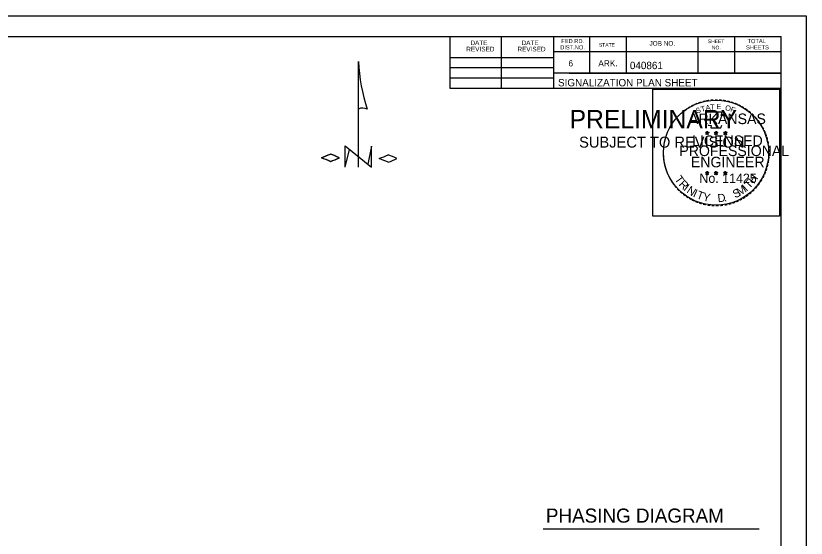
# Model space of a CAD drawing. Extents: x 641001 to 642001, y 326365 to 327005.
# Drawn here: x 641552.4 to 642001.4, y 326708.5 to 327005 of the extents above; entities that cross this region are included whole.
import ezdxf

# ---------------------------------------------------------------- set-up
doc = ezdxf.new("R2010")
doc.units = 0
for name, color, linetype in [('R_Border', 7, 'Continuous'), ('R_Border PE', 7, 'Continuous'), ('R_Border Prem', 7, 'Continuous'), ('R_No Plot', 7, 'Continuous'), ('T_Drafting', 7, 'Continuous'), ('T_Notes', 7, 'Continuous')]:
    doc.layers.add(name, color=color, linetype=linetype)

msp = doc.modelspace()

# ---------------------------------------------------------------- linework, layer by layer
at = {"layer": 'R_Border'}
for p, q in [((641038.57, 326993.34), (641987.11, 326993.34)), ((641799.19, 326963.7), (641799.19, 326993.34)), ((641828.23, 326963.7), (641828.23, 326993.34)), ((641857.81, 326993.34), (641857.81, 326963.7)), ((641878.33, 326993.34), (641878.33, 326972.52)), ((641899.15, 326993.34), (641899.15, 326972.52)), ((641939.89, 326993.34), (641939.89, 326972.52)), ((641960.71, 326993.34), (641960.71, 326972.52)), ((641987.11, 326376.96), (641987.11, 326993.34)), ((641987.11, 326984.52), (641857.81, 326984.52)), ((641987.11, 326984.58), (641987.11, 326984.58)), ((641799.19, 326981.28), (641857.81, 326981.28)), ((641799.19, 326975.7), (641857.81, 326975.7)), ((641799.19, 326969.88), (641857.81, 326969.88)), ((641987.11, 326972.52), (641857.81, 326972.52)), ((641866.69, 326972.52), (641987.11, 326972.52)), ((641987.11, 326963.7), (641799.19, 326963.7))]:
    msp.add_line(p, q, dxfattribs=at)
at = {"layer": 'R_Border PE'}
for p, q in [((641944.09, 326938.78), (641945.13, 326938.45)), ((641944.09, 326938.78), (641944.85, 326938.65)), ((641944.09, 326938.78), (641944.8, 326938.41)), ((641944.49, 326937.56), (641945.13, 326938.45)), ((641944.49, 326937.56), (641944.86, 326938.29)), ((641944.49, 326937.56), (641945.13, 326938.21)), ((641945.13, 326939.54), (641945.01, 326938.79)), ((641945.13, 326938.45), (641945.13, 326939.54)), ((641945.13, 326939.54), (641945.28, 326938.79)), ((641946.18, 326938.78), (641945.13, 326938.45)), ((641945.77, 326937.56), (641945.13, 326938.45)), ((641945.77, 326937.56), (641945.13, 326938.2)), ((641946.18, 326938.78), (641945.32, 326938.63)), ((641945.77, 326937.56), (641945.36, 326938.43)), ((641946.18, 326938.78), (641945.56, 326938.47)), ((641949.1, 326938.78), (641950.14, 326938.45)), ((641949.1, 326938.78), (641949.86, 326938.65)), ((641949.1, 326938.78), (641949.81, 326938.41)), ((641949.5, 326937.56), (641950.14, 326938.45)), ((641949.5, 326937.56), (641949.87, 326938.29)), ((641949.5, 326937.56), (641950.14, 326938.21)), ((641950.14, 326939.54), (641950.02, 326938.79)), ((641950.14, 326938.45), (641950.14, 326939.54)), ((641950.14, 326939.54), (641950.29, 326938.79)), ((641951.19, 326938.78), (641950.14, 326938.45)), ((641950.78, 326937.56), (641950.14, 326938.45)), ((641950.78, 326937.56), (641950.14, 326938.2)), ((641951.19, 326938.78), (641950.33, 326938.63)), ((641950.78, 326937.56), (641950.37, 326938.43)), ((641951.19, 326938.78), (641950.57, 326938.47)), ((641954.39, 326938.74), (641955.44, 326938.41)), ((641954.39, 326938.74), (641955.15, 326938.61)), ((641954.39, 326938.74), (641955.1, 326938.38)), ((641954.79, 326937.52), (641955.44, 326938.41)), ((641954.79, 326937.52), (641955.17, 326938.25)), ((641954.79, 326937.52), (641955.43, 326938.17)), ((641955.44, 326939.51), (641955.31, 326938.75)), ((641956.08, 326937.52), (641955.43, 326938.16)), ((641955.44, 326938.41), (641955.44, 326939.51)), ((641955.44, 326939.51), (641955.58, 326938.76)), ((641956.48, 326938.74), (641955.44, 326938.41)), ((641956.08, 326937.52), (641955.44, 326938.41)), ((641956.48, 326938.74), (641955.62, 326938.6)), ((641956.08, 326937.52), (641955.66, 326938.39)), ((641956.48, 326938.74), (641955.87, 326938.44)), ((641944.08, 326916.06), (641945.12, 326915.73)), ((641944.08, 326916.06), (641944.83, 326915.93)), ((641944.08, 326916.06), (641944.79, 326915.7)), ((641944.47, 326914.84), (641945.12, 326915.73)), ((641944.47, 326914.84), (641944.85, 326915.57)), ((641944.47, 326914.84), (641945.12, 326915.49)), ((641945.12, 326916.82), (641945, 326916.07)), ((641945.12, 326915.73), (641945.12, 326916.82)), ((641945.12, 326916.82), (641945.27, 326916.07)), ((641946.16, 326916.06), (641945.12, 326915.73)), ((641945.76, 326914.84), (641945.12, 326915.73)), ((641945.76, 326914.84), (641945.12, 326915.48)), ((641946.16, 326916.06), (641945.31, 326915.91)), ((641945.76, 326914.84), (641945.35, 326915.71)), ((641946.16, 326916.06), (641945.55, 326915.76)), ((641949.08, 326916.06), (641950.13, 326915.73)), ((641949.08, 326916.06), (641949.84, 326915.93)), ((641949.08, 326916.06), (641949.79, 326915.7)), ((641949.48, 326914.84), (641950.13, 326915.73)), ((641949.48, 326914.84), (641949.86, 326915.57)), ((641949.48, 326914.84), (641950.12, 326915.49)), ((641950.13, 326916.82), (641950.01, 326916.07)), ((641950.77, 326914.84), (641950.12, 326915.48)), ((641950.13, 326915.73), (641950.13, 326916.82)), ((641950.13, 326916.82), (641950.28, 326916.07)), ((641951.17, 326916.06), (641950.13, 326915.73)), ((641950.77, 326914.84), (641950.13, 326915.73)), ((641951.17, 326916.06), (641950.31, 326915.91)), ((641950.77, 326914.84), (641950.36, 326915.71)), ((641951.17, 326916.06), (641950.56, 326915.76)), ((641954.38, 326916.03), (641955.43, 326915.7)), ((641954.38, 326916.03), (641955.14, 326915.9)), ((641954.38, 326916.03), (641955.09, 326915.67)), ((641954.78, 326914.81), (641955.43, 326915.7)), ((641954.78, 326914.81), (641955.16, 326915.54)), ((641954.78, 326914.81), (641955.42, 326915.46)), ((641955.43, 326916.79), (641955.31, 326916.04)), ((641956.07, 326914.81), (641955.42, 326915.45)), ((641955.43, 326915.7), (641955.43, 326916.79)), ((641955.43, 326916.79), (641955.58, 326916.04)), ((641956.47, 326916.03), (641955.43, 326915.7)), ((641956.07, 326914.81), (641955.43, 326915.7)), ((641956.47, 326916.03), (641955.61, 326915.88)), ((641956.07, 326914.81), (641955.66, 326915.68)), ((641956.47, 326916.03), (641955.86, 326915.73))]:
    msp.add_line(p, q, dxfattribs=at)
for points in [[(641944.21, 326950.41), (641945.02, 326947.93)], [(641954.74, 326947.65), (641955.17, 326948.5), (641953.11, 326948.43), (641953.56, 326950.41), (641944.21, 326950.41)], [(641945.69, 326943.15), (641945.69, 326942.88), (641947.38, 326942.83), (641947.21, 326941.41), (641952.82, 326941.41), (641953.43, 326943.02)], [(641945.13, 326939.54), (641945.77, 326937.56), (641944.09, 326938.78), (641946.18, 326938.78), (641944.49, 326937.56), (641945.13, 326939.54)], [(641950.14, 326939.54), (641950.78, 326937.56), (641949.1, 326938.78), (641951.19, 326938.78), (641949.5, 326937.56), (641950.14, 326939.54)], [(641955.44, 326939.51), (641956.08, 326937.52), (641954.39, 326938.74), (641956.48, 326938.74), (641954.79, 326937.52), (641955.44, 326939.51)], [(641945.12, 326916.82), (641945.76, 326914.84), (641944.08, 326916.06), (641946.16, 326916.06), (641944.47, 326914.84), (641945.12, 326916.82)], [(641950.13, 326916.82), (641950.77, 326914.84), (641949.08, 326916.06), (641951.17, 326916.06), (641949.48, 326914.84), (641950.13, 326916.82)], [(641955.43, 326916.79), (641956.07, 326914.81), (641954.38, 326916.03), (641956.47, 326916.03), (641954.78, 326914.81), (641955.43, 326916.79)]]:
    msp.add_lwpolyline(points, dxfattribs=at)
for centre, radius in [((641945.13, 326938.44), 0.517), ((641945.13, 326938.44), 0.434), ((641945.13, 326938.44), 0.347), ((641945.13, 326938.44), 0.297), ((641945.13, 326938.44), 0.224), ((641945.13, 326938.44), 0.149), ((641945.13, 326938.44), 0.0889), ((641950.14, 326938.44), 0.517), ((641950.14, 326938.44), 0.434), ((641950.14, 326938.44), 0.347), ((641950.14, 326938.44), 0.297), ((641950.14, 326938.44), 0.224), ((641950.14, 326938.44), 0.149), ((641950.14, 326938.44), 0.0889), ((641955.43, 326938.41), 0.517), ((641955.43, 326938.41), 0.434), ((641955.43, 326938.41), 0.347), ((641955.43, 326938.41), 0.297), ((641955.43, 326938.41), 0.224), ((641955.43, 326938.41), 0.149), ((641955.43, 326938.41), 0.0889), ((641945.12, 326915.73), 0.517), ((641945.12, 326915.73), 0.434), ((641945.12, 326915.73), 0.347), ((641945.12, 326915.73), 0.297), ((641945.12, 326915.73), 0.224), ((641945.12, 326915.73), 0.149), ((641945.12, 326915.73), 0.0889), ((641950.13, 326915.73), 0.517), ((641950.13, 326915.73), 0.434), ((641950.13, 326915.73), 0.347), ((641950.13, 326915.73), 0.297), ((641950.13, 326915.73), 0.224), ((641950.13, 326915.73), 0.149), ((641950.13, 326915.73), 0.0889), ((641955.43, 326915.7), 0.517), ((641955.43, 326915.7), 0.434), ((641955.43, 326915.7), 0.347), ((641955.43, 326915.7), 0.297), ((641955.43, 326915.7), 0.224), ((641955.43, 326915.7), 0.149), ((641955.43, 326915.7), 0.0889)]:
    msp.add_circle(centre, radius, dxfattribs=at)
at = {"layer": 'R_No Plot'}
for p, q in [((641001.36, 327005.02), (642001.36, 327005.02)), ((641913.94, 326894.65), (641913.94, 326894.65))]:
    msp.add_line(p, q, dxfattribs=at)
for points in [[(641001.34, 327005.02), (642001.36, 327005.02), (642001.36, 326365.01), (641001.34, 326365.01)], [(641914.17, 326963.33), (641986.17, 326963.33), (641986.17, 326891.33), (641914.17, 326891.33)]]:
    msp.add_lwpolyline(points, close=True, dxfattribs=at)
msp.add_circle((641950.17, 326927.33), 29.86, dxfattribs=at)
at = {"layer": 'T_Drafting'}
for p, q in [((641747.04, 326919.07), (641747.04, 326979.05)), ((641739.53, 326919.09), (641742, 326929.13)), ((641739.54, 326919.07), (641739.54, 326931.26)), ((641739.54, 326931.26), (641754.53, 326919.07)), ((641754.53, 326931.04), (641752.4, 326920.84)), ((641754.53, 326919.07), (641754.53, 326931.04)), ((641754.53, 326931.02), (641754.53, 326931.04))]:
    msp.add_line(p, q, dxfattribs=at)
for centre, radius, start, end in [((641844.83, 326982.98), 97.82, 182.2815, 198.4669), ((641749.4, 326947.12), 5.53, 61.6986, 115.682), ((641661.48, 327088.44), 176.2, 291.4742, 293.2539), ((641661.48, 326760.45), 176.2, 66.7461, 68.5258), ((641661.71, 327088.44), 176.2, 291.4742, 293.2539), ((641661.71, 326760.45), 176.2, 66.7461, 68.5258), ((641702.8, 326852.88), 78.93, 65.1071, 68.9839), ((641702.8, 326996.01), 78.93, 291.0161, 294.8929), ((641703.03, 326852.88), 78.93, 65.1071, 68.9839), ((641703.03, 326996.01), 78.93, 291.0161, 294.8929), ((641694.34, 327087.98), 176.2, 291.4742, 293.2539), ((641694.34, 326759.99), 176.2, 66.7461, 68.5258), ((641735.65, 326852.42), 78.93, 65.1071, 68.9839), ((641735.65, 326995.55), 78.93, 291.0161, 294.8929)]:
    msp.add_arc(centre, radius, start, end, dxfattribs=at)
at = {"layer": 'T_Notes'}
msp.add_line((641851.95, 326713.82), (641974.59, 326713.82), dxfattribs=at)

# ---------------------------------------------------------------- texts
at = {"layer": 'R_Border'}
for s, height, p in [('FED.RD.', 2.346, (641862.25, 326989.5)), ('SHEET', 2.052, (641945.47, 326989.5)), ('TOTAL', 2.346, (641968.03, 326989.5)), ('REVISED', 2.638, (641808.31, 326984.82)), ('DATE', 2.638, (641810.65, 326988.36)), ('REVISED', 2.638, (641837.35, 326984.82)), ('DATE', 2.638, (641839.69, 326988.36)), ('DIST.NO.', 2.346, (641861.65, 326985.96)), ('STATE', 2.052, (641883.61, 326987.46)), ('JOB NO.', 2.638, (641912.35, 326988.06)), ('NO.', 2.052, (641947.81, 326985.96)), ('SHEETS', 2.346, (641967.19, 326985.96)), ('6', 3.52, (641866.33, 326976.3)), ('ARK.', 3.517, (641883.31, 326976.3)), ('040861', 4.2, (641901.23, 326974.74)), ('SIGNALIZATION PLAN SHEET', 4.2, (641860.4, 326964.99))]:
    msp.add_text(s, height=height, dxfattribs=at).set_placement(p)
at = {"layer": 'R_Border PE'}
for s, height, rotation, p in [('-', 4.8, 24.3072, (641938.55, 326952.99)), ('-', 4.8, 19.1761, (641940.45, 326953.8)), ('-', 4.8, 13.6302, (641942.7, 326954.52)), ('-', 4.8, 10.2193, (641944.74, 326955)), ('-', 4.8, 5.8968, (641946.93, 326955.33)), ('-', 4.8, 0.1862, (641949.24, 326955.55)), ('-', 4.8, 357.743, (641951.41, 326955.51)), ('-', 4.8, 352.1617, (641953.64, 326955.34)), ('-', 4.8, 347.2049, (641955.8, 326955)), ('-', 4.8, 342.3362, (641957.7, 326954.54)), ('-', 4.8, 337.8551, (641959.91, 326953.87)), ('-', 4.8, 38.9507, (641931.7, 326948.61)), ('-', 4.8, 36.2317, (641933.13, 326949.74)), ('-', 4.8, 34.0636, (641934.86, 326950.93)), ('-', 4.8, 28.7918, (641936.65, 326952.04)), ('S', 3, 21.594, (641939.28, 326949.45)), ('T', 3, 16.4036, (641942.02, 326950.44)), ('A', 3, 11.2132, (641944.5, 326951.19)), ('T', 3, 6.0228, (641947.04, 326951.69)), ('E', 3, 0.8323, (641950.36, 326952.02)), ('O', 3, 350.4515, (641955.17, 326951.39)), ('F', 3, 340.0707, (641958.03, 326950.71)), ('-', 4.8, 334.1211, (641961.8, 326953.05)), ('-', 4.8, 329.6409, (641963.54, 326952.21)), ('-', 4.8, 325.8627, (641965.47, 326951.12)), ('-', 4.8, 320.5297, (641967.3, 326949.84)), ('-', 4.8, 50.6142, (641927.85, 326944.47)), ('-', 4.8, 48.4231, (641929.06, 326945.92)), ('-', 4.8, 42.9622, (641930.4, 326947.36)), ('-', 4.8, 315.5786, (641969.1, 326948.38)), ('-', 4.8, 309.8797, (641970.8, 326946.73)), ('-', 4.8, 62.8713, (641924.7, 326939.34)), ('-', 4.8, 58.0706, (641925.63, 326941.18)), ('-', 4.8, 54.2325, (641926.61, 326942.76)), ('-', 4.8, 306.6522, (641972.38, 326944.92)), ('-', 4.2, 303.6753, (641973.84, 326943.22)), ('-', 4.8, 299.6684, (641974.79, 326941.4)), ('-', 4.8, 72.3945, (641923.26, 326935.62)), ('-', 4.8, 67.7743, (641923.92, 326937.51)), ('-', 4.8, 294.6628, (641975.76, 326939.56)), ('-', 4.8, 290.5728, (641976.54, 326937.83)), ('-', 4.8, 81.2013, (641922.27, 326931.34)), ('-', 4.8, 75.461, (641922.67, 326933.48)), ('-', 4.8, 285.1233, (641977.24, 326936.09)), ('-', 4.8, 280.5493, (641977.84, 326933.87)), ('-', 4.8, 89.0622, (641921.97, 326927.16)), ('-', 4.8, 85.1863, (641922.05, 326929.26)), ('-', 4.8, 276.5962, (641978.32, 326931.56)), ('-', 4.8, 274.3301, (641978.5, 326929.4)), ('-', 4.8, 94.1959, (641922.08, 326924.99)), ('-', 4.8, 98.9479, (641922.29, 326922.99)), ('-', 4.8, 263.5172, (641978.55, 326925.5)), ('-', 4.8, 269.9407, (641978.61, 326927.5)), ('-', 4.8, 101.7149, (641922.7, 326920.79)), ('-', 4.8, 105.4578, (641923.18, 326919)), ('-', 4.8, 255.7626, (641978.01, 326921.51)), ('-', 4.8, 260.9953, (641978.34, 326923.54)), ('-', 4.8, 109.0874, (641923.83, 326917.11)), ('-', 4.8, 114.0643, (641924.59, 326915.32)), ('H', 4.62, 54.6088, (641971.76, 326909.35)), ('-', 4.8, 247.8887, (641976.79, 326917.33)), ('-', 4.8, 252.8681, (641977.46, 326919.35)), ('-', 4.8, 115.7289, (641925.51, 326913.47)), ('-', 4.8, 120.4471, (641926.58, 326911.71)), ('-', 4.8, 125.8934, (641927.79, 326910.03)), ('T', 4.62, 306.0406, (641926.4, 326912.24)), ('R', 4.62, 314.005, (641928.69, 326909.1)), ('T', 4.62, 46.6444, (641969.09, 326906.52)), ('-', 4.8, 239.0712, (641974.83, 326913.18)), ('-', 4.8, 244.6197, (641976.01, 326915.44)), ('-', 4.8, 130.7181, (641929.17, 326908.37)), ('-', 4.8, 134.2238, (641930.72, 326906.73)), ('I', 4.62, 321.9694, (641931.39, 326906.3)), ('N', 4.62, 326.5002, (641933.09, 326904.89)), ('I', 4.62, 335.3603, (641936.72, 326902.53)), ('S', 4.62, 26.9312, (641961.04, 326901.33)), ('M', 4.62, 32.6563, (641963.56, 326902.55)), ('I', 4.62, 42.1136, (641967.41, 326905.09)), ('-', 4.8, 225.7653, (641970.89, 326907.84)), ('-', 4.8, 231.2538, (641972.33, 326909.53)), ('-', 4.8, 233.8452, (641973.62, 326911.23)), ('-', 4.8, 138.9338, (641932.3, 326905.34)), ('-', 4.8, 144.6463, (641933.97, 326904.12)), ('-', 4.8, 148.0898, (641935.65, 326903.01)), ('-', 4.8, 151.5704, (641937.39, 326902.04)), ('T', 4.62, 339.8912, (641938.7, 326901.55)), ('Y', 4.62, 347.8556, (641942.35, 326900.21)), ('D', 4.62, 6.3969, (641951.3, 326899.14)), ('-', 4.8, 212.2491, (641966.08, 326903.73)), ('-', 4.8, 215.7363, (641967.68, 326904.89)), ('-', 4.8, 221.0851, (641969.33, 326906.31)), ('-', 4.8, 154.6002, (641938.95, 326901.3)), ('-', 4.8, 158.5612, (641940.82, 326900.53)), ('-', 4.8, 162.7983, (641942.88, 326899.89)), ('-', 4.8, 167.5555, (641945.03, 326899.4)), ('-', 4.8, 173.1155, (641947.35, 326899.07)), ('-', 4.8, 176.5183, (641949.59, 326898.91)), ('-', 4.8, 181.5918, (641951.82, 326898.97)), ('-', 4.8, 185.8167, (641954.25, 326899.2)), ('-', 4.8, 191.2858, (641956.46, 326899.59)), ('.', 4.62, 13.7642, (641954.88, 326899.52)), ('-', 4.8, 195.4743, (641958.64, 326900.19)), ('-', 4.8, 200.7184, (641960.67, 326900.92)), ('-', 4.8, 204.2516, (641962.53, 326901.74)), ('-', 4.8, 207.3568, (641964.4, 326902.69))]:
    msp.add_text(s, height=height, rotation=rotation, dxfattribs=at).set_placement(p)
for s, height, p in [('ARKANSAS', 6, (641934.77, 326943.55)), ('DWB', 0.03, (641945.1, 326938.43)), ('DWB', 0.03, (641950.11, 326938.43)), ('DWB', 0.03, (641955.4, 326938.4)), ('LICENSED', 6, (641936.56, 326931.1)), ('PROFESSIONAL', 6, (641929.29, 326925.39)), ('ENGINEER', 6, (641935.85, 326919.02)), ('No. 11425', 5.271, (641940.73, 326910.16)), ('DWB', 0.03, (641945.08, 326915.71)), ('DWB', 0.03, (641950.09, 326915.71)), ('DWB', 0.03, (641955.39, 326915.68))]:
    msp.add_text(s, height=height, dxfattribs=at).set_placement(p)
at = {"layer": 'R_Border Prem'}
for s, height, p in [('PRELIMINARY', 10.5, (641866.96, 326941.09)), ('SUBJECT TO REVISION', 6.2253, (641872.39, 326930.2))]:
    msp.add_text(s, height=height, dxfattribs=at).set_placement(p)
at = {"layer": 'T_Notes'}
msp.add_text('PHASING DIAGRAM', height=8, dxfattribs=at).set_placement((641853.54, 326717.29))

doc.saveas('drawing.dxf')
